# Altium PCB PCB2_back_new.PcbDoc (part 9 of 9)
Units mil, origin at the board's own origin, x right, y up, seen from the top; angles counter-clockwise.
Board outline 6299 x 3937 mil, 4 copper layers (TopLayer, GROUND, VCC, BottomLayer); 253 components, 421 nets, 2085 pads, 712 vias.
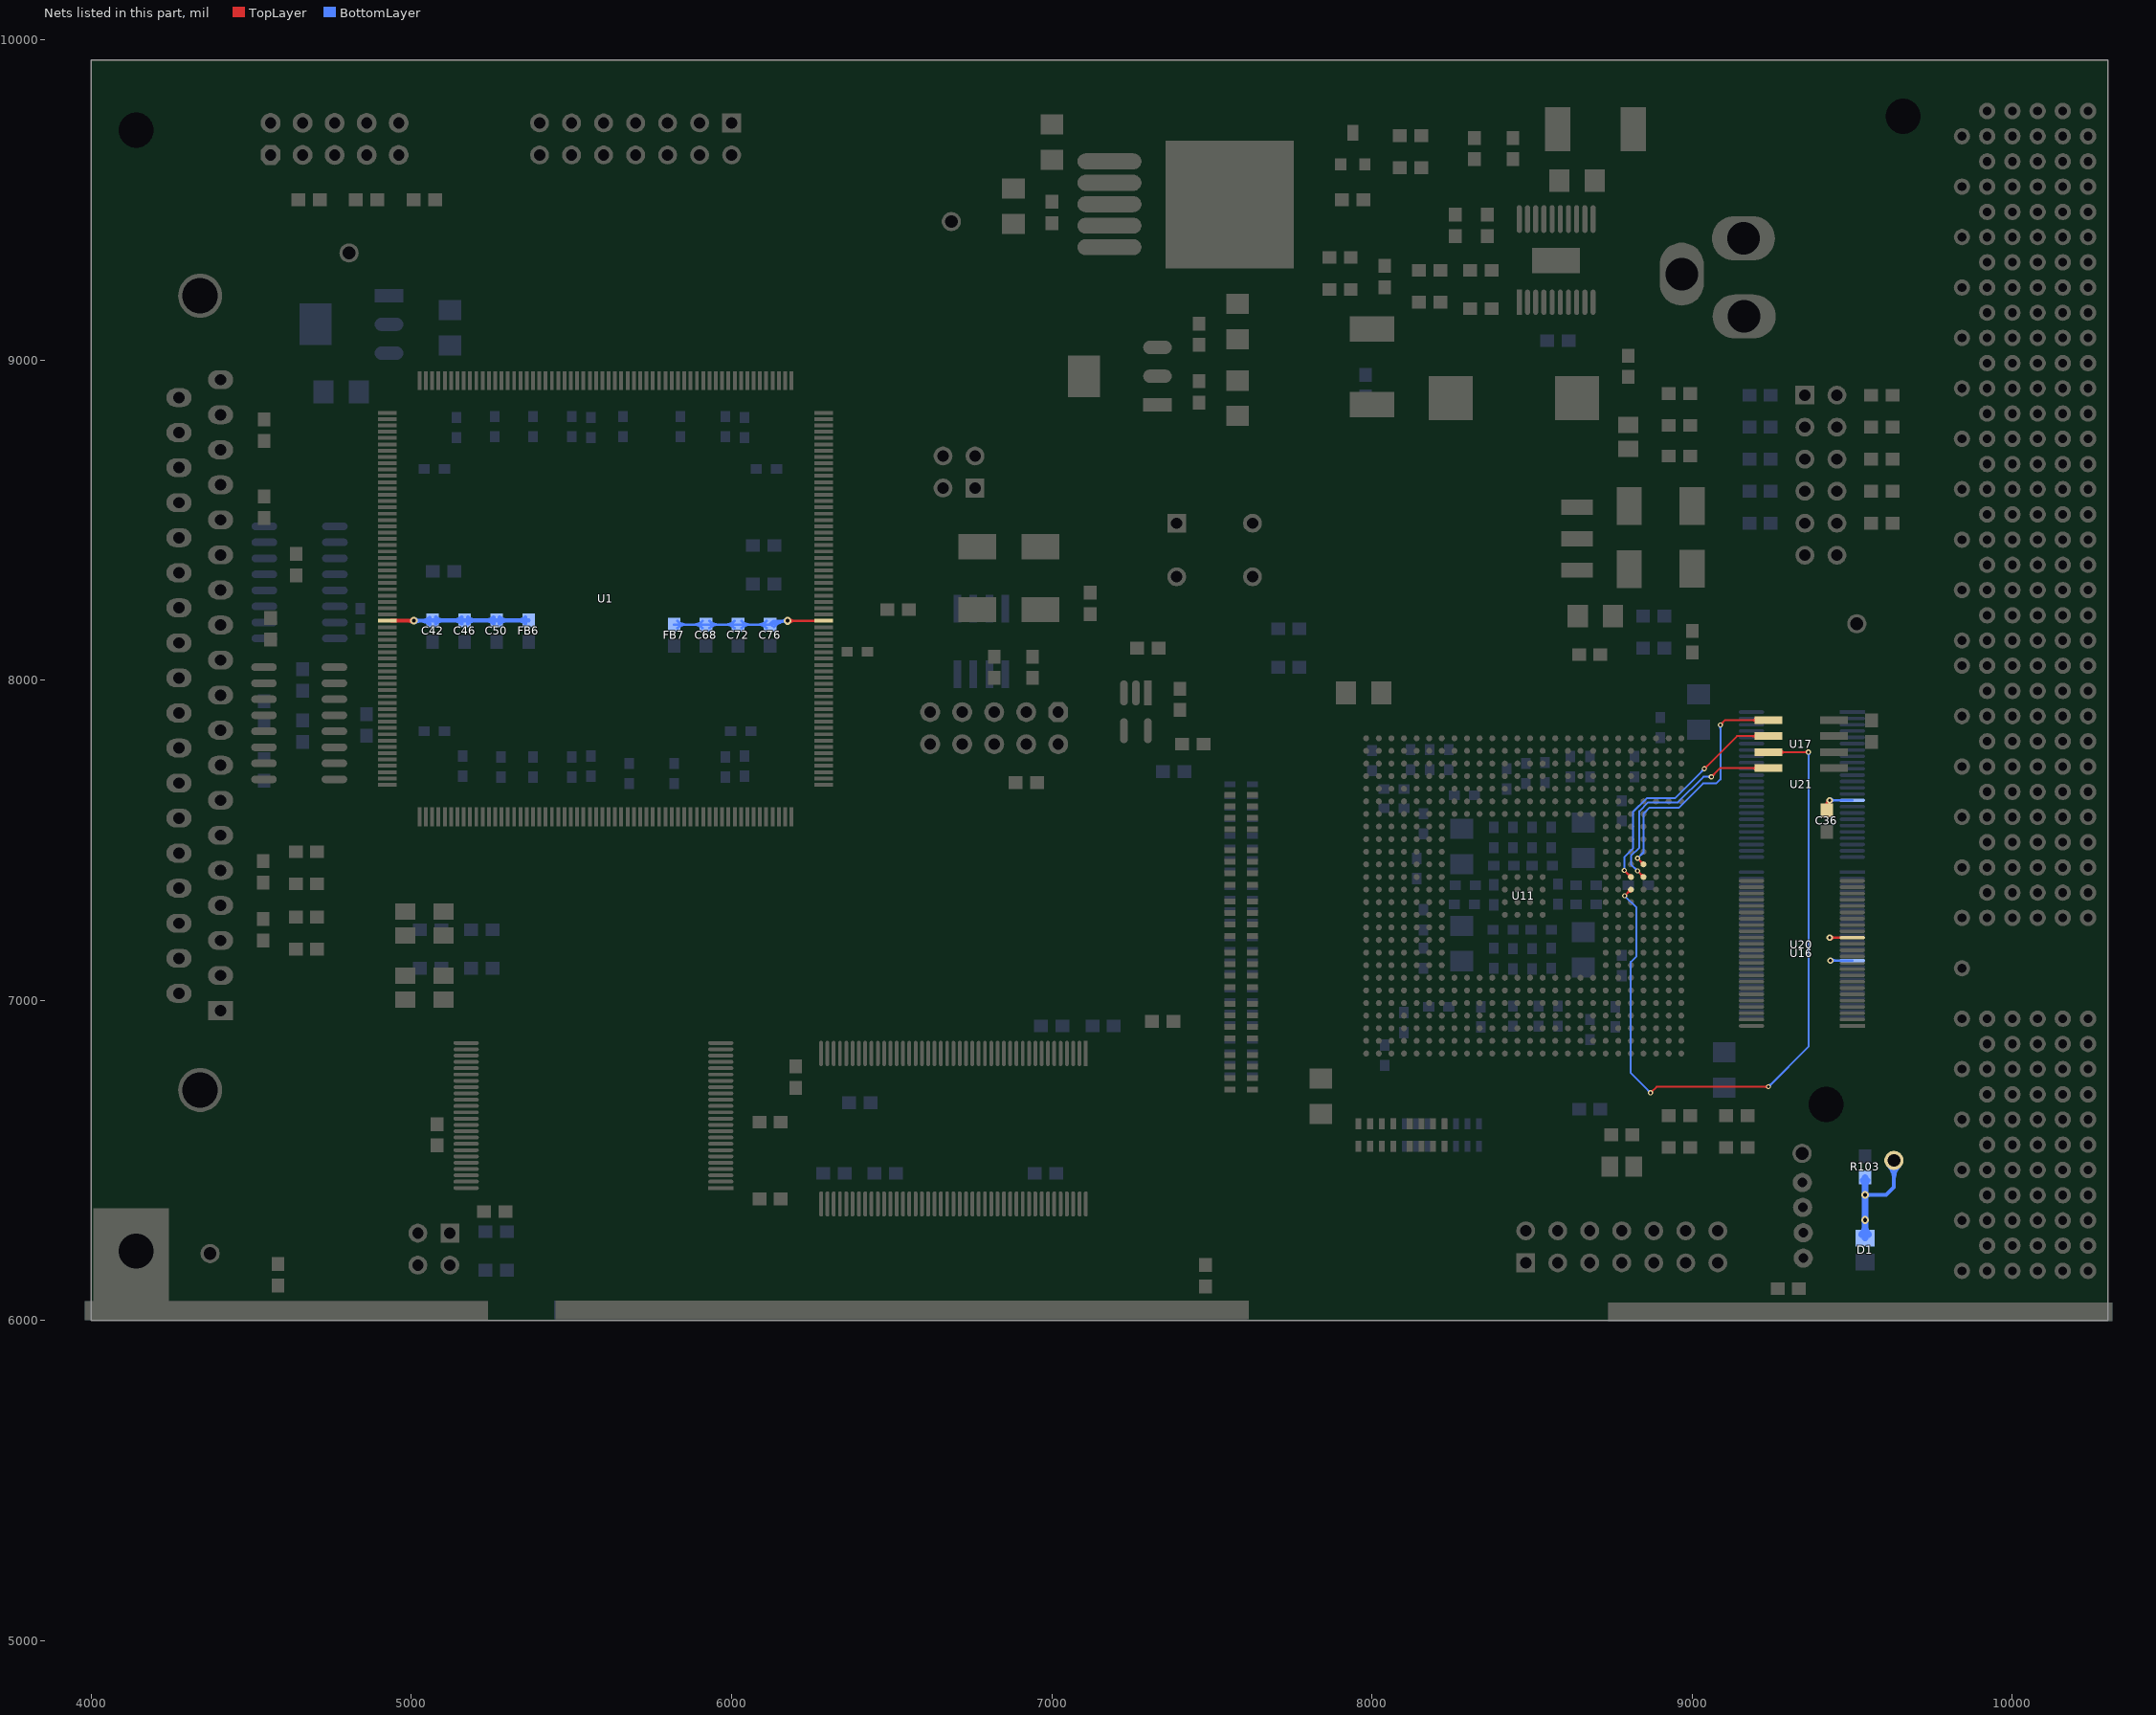
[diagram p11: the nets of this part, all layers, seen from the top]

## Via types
v1: diameter 16, hole 8, TopLayer to BottomLayer, 311 vias
v2: diameter 20, hole 10, TopLayer to BottomLayer, 202 vias
v3: diameter 24, hole 12, TopLayer to BottomLayer, 179 vias
v4: diameter 40, hole 20, TopLayer to BottomLayer, 12 vias
v5: diameter 30, hole 15, TopLayer to BottomLayer, 8 vias

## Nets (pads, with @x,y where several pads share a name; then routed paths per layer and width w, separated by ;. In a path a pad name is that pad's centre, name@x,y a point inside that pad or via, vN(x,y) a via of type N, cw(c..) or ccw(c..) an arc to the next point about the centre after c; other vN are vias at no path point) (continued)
V16210: C36.2 D1.2 pad.0@9630,6500 R103.1 U16.15 U20.15 U21.15 | length 966
  TopLayer w8: C36.2@9420,7592.07 cw(c9455.65,7592.07) v2@9433.19,7619.75 ; C36.2@9420,7593.46 C36.2@9420,7615 ; C36.2@9420,7608.86 cw(c9442.03,7608.86) v2@9428.15,7625.96 ; v2@9423.42,7624.04 cw(c9411.69,7623.31) C36.2@9420,7615 ; v2@9429.04,7618.42 ccw(c9428.31,7606.69) C36.2@9420,7615 ; v2(9429.41,7195.59) U16.15@9500,7195.59 ; v2(9429.41,7624.41) C36.2@9420,7615 ; v2@9433.65,7191.35 cw(c9443.9,7181.1) 9443.9,7195.59 cw(c9443.9,7210.08) v2@9433.65,7199.83
  BottomLayer w8: v2(9429.41,7624.41) U21.15@9500,7624.41 ; v2(9431.59,7124.41) U20.15@9500,7124.41 ; v2@9433.65,7620.17 cw(c9443.9,7609.92) 9443.9,7624.41 cw(c9443.9,7638.9) v2@9433.65,7628.65 ; v2@9435.83,7120.17 cw(c9446.08,7109.92) 9446.08,7124.41 cw(c9446.08,7138.9) v2@9435.83,7128.65
  BottomLayer w12: v3(9540,6392) 9605,6392 9630,6417 pad.0@9630,6500 ; v3@9544.24,6387.76 cw(c9554.49,6377.51) 9554.49,6392 cw(c9554.49,6406.49) v3@9544.24,6396.24 ; pad.0@9613.03,6483.03 cw(c9572.06,6442.06) 9630,6442.06 cw(c9687.94,6442.06) pad.0@9646.97,6483.03
  BottomLayer w20: D1.2@9528.98,6268.43 ccw(c9502.36,6295.04) 9540,6295.04 ccw(c9577.64,6295.04) D1.2@9551.02,6268.43 ; R103.1@9533.15,6437.72 cw(c9516.62,6421.19) 9540,6421.19 cw(c9563.38,6421.19) R103.1@9546.85,6437.72 ; D1.2@9540,6257.4 R103.1@9540,6446.54
  other v3: 9540,6314
VCCA_PLL1: C68.2 C72.1 C76.2 FB7.2 U1.27 | length 997.5
  TopLayer w8: v3(6175,8185) U1.27@6287.1,8185.1 ; v3@6180.66,8179.35 cw(c6194.33,8165.7) 6194.31,8185.02 cw(c6194.3,8204.33) v3@6180.65,8190.66
  BottomLayer w8: FB7.2@5820,8173.46 C76.2@6120,8173.46 6131.54,8185 v3(6175,8185) ccw(c6175,8128.17) C76.2@6131.9,8165.21 ; FB7.2@5831.09,8162.37 cw(c5857.87,8135.6) 5857.87,8173.46 cw(c5857.87,8211.33) FB7.2@5831.09,8184.56 ; C68.2@5908.91,8162.37 ccw(c5882.13,8135.6) 5882.13,8173.46 ccw(c5882.13,8211.33) C68.2@5908.91,8184.56 ; C68.2@5931.09,8162.37 cw(c5957.87,8135.6) 5957.87,8173.46 cw(c5957.87,8211.33) C68.2@5931.09,8184.56 ; C72.1@6008.91,8162.37 ccw(c5982.13,8135.6) 5982.13,8173.46 ccw(c5982.13,8211.33) C72.1@6008.91,8184.56 ; C72.1@6031.09,8162.37 cw(c6057.87,8135.6) 6057.87,8173.46 cw(c6057.87,8211.33) C72.1@6031.09,8184.56 ; C76.2@6108.91,8162.37 ccw(c6082.13,8135.6) 6082.13,8173.46 ccw(c6082.13,8211.33) C76.2@6108.91,8184.56 ; C76.2@6119.76,8175.64 cw(c6140.15,8158.12) 6140.15,8185 ; C76.2@6125.83,8170.42 cw(c6157.57,8143.14) 6157.57,8185 ; v3@6169.34,8179.34 ccw(c6155.69,8165.69) 6155.69,8185 ccw(c6155.69,8204.31) v3@6169.34,8190.66
VCCA_PLL2: C42.2 C46.2 C50.1 FB6.2 U1.154 | length 837.7
  TopLayer w12: U1.154@4937.69,8185.1 v3(5008.1,8185.1) ; v3@5003.86,8180.86 ccw(c4993.62,8170.62) 4993.62,8185.1 ccw(c4993.62,8199.59) v3@5003.86,8189.34
  BottomLayer w8: C42.2@5064.64,8185.1 C42.2@5066,8186.46
  BottomLayer w12: v3(5008.1,8185.1) C42.2@5064.64,8185.1 ; v3@5012.34,8180.86 cw(c5022.59,8170.62) 5022.59,8185.1 cw(c5022.59,8199.59) v3@5012.34,8189.34 ; 5031.5,8185.1 cw(c5031.5,8149.99) C42.2@5056.32,8174.82 ; 5034.43,8185.1 ccw(c5034.43,8216.07) C42.2@5056.32,8194.17 ; C42.2@5066,8186.46 FB6.2@5366,8186.46 ; C42.2@5075.68,8176.79 cw(c5099.04,8153.43) 5099.04,8186.46 cw(c5099.04,8219.5) C42.2@5075.68,8196.14 ; C46.2@5156.32,8176.79 ccw(c5132.96,8153.43) 5132.96,8186.46 ccw(c5132.96,8219.5) C46.2@5156.32,8196.14 ; C46.2@5175.68,8176.79 cw(c5199.04,8153.43) 5199.04,8186.46 cw(c5199.04,8219.5) C46.2@5175.68,8196.14 ; C50.1@5256.32,8176.79 ccw(c5232.96,8153.43) 5232.96,8186.46 ccw(c5232.96,8219.5) C50.1@5256.32,8196.14 ; C50.1@5275.68,8176.79 cw(c5299.04,8153.43) 5299.04,8186.46 cw(c5299.04,8219.5) C50.1@5275.68,8196.14 ; FB6.2@5356.32,8176.79 ccw(c5332.96,8153.43) 5332.96,8186.46 ccw(c5332.96,8219.5) FB6.2@5356.32,8196.14
XSPCLK: U11.R5 U17.2 | length 838.4
  TopLayer w6: v1(8788,7405.7) U11.R5@8808.52,7385.18 ; U11.R5@8802.27,7385.18 ccw(c8787.17,7385.18) 8797.85,7395.85 ccw(c8808.52,7406.53) U11.R5@8808.52,7391.43 ; v1(9038,7723) 9140,7825 U17.2@9237.64,7825 ; v1@9038,7728 ccw(c9038,7740.07) 9046.54,7731.54 ccw(c9055.07,7723) v1@9043,7723 ; U17.2@9199.91,7818.77 ccw(c9184.87,7803.73) 9184.87,7825 ccw(c9184.87,7846.27) U17.2@9199.91,7831.23
  BottomLayer w6: v1(8788,7405.7) 8788,7447 8815,7474 8815,7588 8858,7631 8946,7631 v1(9038,7723) ; v1@9033,7723 cw(c9020.93,7723) 9029.46,7714.46 cw(c9038,7705.93) v1@9038,7718
XSPCS: U11.T4 U17.1 | length 879.4
  TopLayer w6: v1(8829,7443.44) U11.T4@8847.89,7424.55 ; U11.T4@8841.64,7424.55 ccw(c8826.54,7424.55) 8837.22,7435.22 ccw(c8847.89,7445.9) U11.T4@8847.89,7430.8 ; v1(9088,7860) 9103,7875 U17.1@9237.64,7875 ; v1@9088,7865 ccw(c9088,7877.07) 9096.54,7868.54 ccw(c9105.07,7860) v1@9093,7860 ; U17.1@9199.91,7868.77 ccw(c9184.87,7853.73) 9184.87,7875 ccw(c9184.87,7896.27) U17.1@9199.91,7881.23
  BottomLayer w6: v1(8829,7443.44) 8848,7462.44 8848,7583 8867,7602 8959,7602 9034,7677 9075,7677 9088,7690 v1(9088,7860) ; v1@9084.46,7856.46 cw(c9075.93,7847.93) 9088,7847.93 cw(c9100.07,7847.93) v1@9091.54,7856.46
XSPDI: U11.R4 U17.4 | length 785.9
  TopLayer w6: v1(8829,7404.07) U11.R4@8847.89,7385.18 ; U11.R4@8841.64,7385.18 ccw(c8826.54,7385.18) 8837.22,7395.85 ccw(c8847.89,7406.53) U11.R4@8847.89,7391.43 ; v1(9060,7698) 9087,7725 U17.4@9237.64,7725 ; v1@9060,7703 ccw(c9060,7715.07) 9068.54,7706.54 ccw(c9077.07,7698) v1@9065,7698 ; U17.4@9199.91,7718.77 ccw(c9184.87,7703.73) 9184.87,7725 ccw(c9184.87,7746.27) U17.4@9199.91,7731.23
  BottomLayer w6: v1(8829,7404.07) 8809,7424.07 8809,7451.03 8834.82,7476.85 8834.82,7590.82 8862,7618 8955,7618 9035,7698 v1(9060,7698) ; v1@9056.46,7694.46 ccw(c9047.93,7685.93) 9047.93,7698 ccw(c9047.93,7710.07) v1@9056.46,7701.54
XSPDO: U11.P5 U17.3 | length 2461.1
  TopLayer w6: v1(8789,7326.29) U11.P5@8808.52,7345.81 ; U11.P5@8802.27,7345.81 cw(c8787.17,7345.81) 8797.85,7335.14 cw(c8808.52,7324.47) U11.P5@8808.52,7339.56 ; v1(8870,6711) 8889,6730 v1(9238,6730) ; v1@8870,6716 ccw(c8870,6728.07) 8878.54,6719.54 ccw(c8887.07,6711) v1@8875,6711 ; v1@9234.46,6726.46 ccw(c9225.93,6717.93) 9225.93,6730 ccw(c9225.93,6742.07) v1@9234.46,6733.54 ; U17.3@9237.64,7775 v1(9363,7775) ; U17.3@9275.36,7768.77 cw(c9290.41,7753.73) 9290.41,7775 cw(c9290.41,7796.27) U17.3@9275.36,7781.23 ; v1@9359.46,7771.46 ccw(c9350.93,7762.93) 9350.93,7775 ccw(c9350.93,7787.07) v1@9359.46,7778.54
  BottomLayer w6: v1(8789,7326.29) 8826,7289.29 8826,7138 8808,7120 8808,6773 v1(8870,6711) ; v1@8865,6711 ccw(c8852.93,6711) 8861.46,6719.54 ccw(c8870,6728.07) v1@8870,6716 ; v1(9238,6730) 9364,6856 9364,7774 v1(9363,7775) ; v1@9238,6735 ccw(c9238,6747.07) 9246.54,6738.54 ccw(c9255.07,6730) v1@9243,6730 ; v1@9359.46,7771.46 cw(c9348.51,7760.51) 9364,7760.51 ; 9364,7765.34 cw(c9372.66,7765.34) v1@9366.54,7771.46
pads on no net: J2.6 J4.A15 J4.A17 J4.A19 J4.A21 J4.A23 J4.C8 J4.C10 J4.C16 J4.C18 J4.C20 J4.C22 J4.C24 J4.D25 J5.A1 J5.A2 J5.A3 J5.A4 J5.A5 J5.A6 J5.A7 J5.A8 J5.A9 J5.A10 J5.A11 J5.A12 J5.A13 J5.A14 J5.A15 J5.A19 J5.A20 J5.A21 J5.A22 J5.B2 J5.B4 J5.B5 J5.B6 J5.B8 J5.B10 J5.B12 J5.B14 J5.B19 J5.B20 J5.B21 J5.B22 J5.C1 J5.C2 J5.C3 J5.C4 J5.C5 J5.C6 J5.C7 J5.C8 J5.C9 J5.C10 J5.C11 J5.C12 J5.C13 J5.C14 J5.C15 J5.C16 J5.C17 J5.C19 J5.C20 J5.C21 J5.C22 J5.D1 J5.D2 J5.D3 J5.D5 J5.D7 J5.D9 J5.D11 J5.D13 J5.D15 J5.D19 J5.D21 J5.D22 J5.E1 J5.E2 J5.E3 J5.E4 J5.E5 J5.E6 J5.E7 J5.E8 J5.E9 J5.E10 J5.E11 J5.E12 J5.E13 J5.E14 J5.E15 J5.E19 J5.E20 J5.E21 J5.E22 JP1.0 JP1.2 JP1.3 JP1.17 JP1.19 JP1.21 JP1.35 JP1.37 JP8.6 JP8.7 JP8.8 S2.3 S2.4 U1.23 U1.38 U1.45 U1.46 U1.47 U1.48 U1.49 U1.50 U1.53 U1.54 U1.55 U1.56 U1.57 U1.58 U1.59 U1.60 U1.61 U1.62 U1.63 U1.64 U1.65 U1.66 U1.67 U1.68 U1.73 U1.74 U1.75 U1.76 U1.77 U1.78 U1.79 U1.104 U1.105 U1.106 U1.107 U1.108 U1.113 U1.114 U1.115 U1.116 U1.117 U1.118 U1.119 U1.120 U1.121 U1.122 U1.123 U1.124 U1.125 U1.126 U1.127 U1.128 U1.131 U1.132 U1.133 U1.134 U1.135 U1.138 U1.143 U1.144 U1.156 U1.158 U1.164 U1.165 U1.166 U1.167 U1.168 U1.169 U1.170 U1.175 U1.176 U2.9 U2.10 U2.13 U2.14 U2.15 U2.30 U2.32 U2.34 U2.36 U2.39 U2.41 U2.43 U4.14 U4.30 U4.57 U4.69 U4.70 U4.73 U6.1 U7.5 U11.A4 U11.A5 U11.A7 U11.A9 U11.A10 U11.A11 U11.A13 U11.A17 U11.AA2 U11.AA3 U11.AA23 U11.AA24 U11.AA25 U11.AA26 U11.AB3 U11.AB11 U11.AB12 U11.AB13 U11.AB14 U11.AB15 U11.AB16 U11.AB23 U11.AB24 U11.AB25 U11.AC1 U11.AC4 U11.AC6 U11.AC7 U11.AC8 U11.AC9 U11.AC10 U11.AC11 U11.AC12 U11.AC13 U11.AC14 U11.AC15 U11.AC16 U11.AC17 U11.AC19 U11.AC20 U11.AC21 U11.AC25 U11.AC26 U11.AD3 U11.AD5 U11.AD6 U11.AD7 U11.AD8 U11.AD9 U11.AD10 U11.AD11 U11.AD12 U11.AD13 U11.AD14 U11.AD15 U11.AD16 U11.AD17 U11.AD19 U11.AD20 U11.AD21 U11.AD22 U11.AD23 U11.AD25 U11.AD26 U11.AE5 U11.AE6 U11.AE7 U11.AE9 U11.AE11 U11.AE15 U11.AE16 U11.AE17 U11.AE18 U11.AE20 U11.AE21 U11.AE22 U11.AE23 U11.AF3 U11.AF4 U11.AF5 U11.AF6 U11.AF8 U11.AF10 U11.AF12 U11.AF14 U11.AF16 U11.AF17 U11.AF18 U11.AF20 U11.AF21 U11.AF23 U11.AF24 U11.B8 U11.B9 U11.B10 U11.B11 U11.B12 U11.B15 U11.B16 U11.B17 U11.C7 U11.C8 U11.C9 U11.C10 U11.C11 U11.C12 U11.C15 U11.C16 U11.C17 U11.D6 U11.D7 U11.D8 U11.D9 U11.D10 U11.D11 U11.D12 U11.D15 U11.D16 U11.D17 U11.E11 U11.E12 U11.E13 U11.E14 U11.L22 U11.M5 U11.M22 U11.N22 U11.P22 U11.R22 U11.R25 U11.R26 U11.T22 U11.T23 U11.W7 U11.W23 U11.W24 U11.Y23 U11.Y24 U11.Y25 U11.Y26 U15.1 U16.1 U17.6 U17.7 U20.1 U21.1 U21.36 U21.37 U21.38 U21.39 U21.40 U21.42 U21.43 U21.44 U21.45 U21.46

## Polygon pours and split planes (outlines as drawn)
GND on GROUND (split plane): 10266.92,6032.08 4243,6032.08 4243,6324 4026.08,6324 4026.08,9610 4245,9610 4245,9906.92 10266.92,9906.92
V3.3 on VCC (split plane): 296 vertices, not listed, extent 4086.08,6085.08 9679.93,9855.92
V5 on VCC (split plane): 10262.92,6085.08 9358.07,6085.08 9358.07,6254.93 9695,6254.93 9697.94,6255.22 9700.77,6256.07 9703.37,6257.47 9705.66,6259.34 9707.53,6261.63 9708.93,6264.23 9709.78,6267.06 9710.07,6270 9710.07,7694 9710.07,8111 9709.78,8113.94 9708.93,8116.77 9707.53,8119.37 9705.66,8121.66 9703.37,8123.53 9700.77,8124.93 9697.94,8125.78 9695,8126.07 9251.07,8126.07 9251.07,8972 9250.78,8974.94 9249.93,8977.77 9248.53,8980.37 9246.66,8982.66 9244.37,8984.53 9241.77,8985.93 9238.94,8986.78 9236,8987.07 8257,8987.07 8256.99,8987.07 7800.99,8986.77 7800.94,8986.78 7798,8987.07 7795.06,8986.78 7795,8986.76 6754.99,8986.07 6753.49,8985.92 6752.06,8985.78 6752.05,8985.78 6750.66,8985.36 6749.54,8985.02 6749,8985.07 4956.07,8985.07 4956.07,9145.93 7334,9145.93 7336.94,9146.22 7339.77,9147.07 7342.37,9148.47 7344.66,9150.34 7346.53,9152.63 7347.93,9155.23 7348.78,9158.06 7349.07,9161 7349.07,9483 7348.78,9485.94 7347.93,9488.77 7346.53,9491.37 7344.66,9493.66 7342.37,9495.53 7339.77,9496.93 7336.94,9497.78 7334,9498.07 6894.07,9498.07 6894.07,9855.92 10262.92,9855.92
V1.5 on VCC (split plane): 7782.93,8911 7782.93,8599.07 7627,8599.07 7624.06,8598.78 7621.23,8597.93 7618.63,8596.53 7616.34,8594.66 7388.76,8367.07 6535,8367.07 6532.06,8366.78 6529.23,8365.93 6526.63,8364.53 6524.34,8362.66 6007.34,7845.66 6005.47,7843.37 6004.07,7840.77 6003.22,7837.94 6002.93,7835 6002.93,7706.07 5206.07,7706.07 5206.07,7884.76 5281.66,7960.34 5283.53,7962.63 5284.93,7965.23 5285.78,7968.06 5286.07,7971 5286.07,8328 5285.78,8330.94 5284.93,8333.77 5283.53,8336.37 5281.66,8338.66 5177.07,8443.24 5177.07,8798.93 6114.93,8798.93 6114.93,8594 6115.22,8591.06 6116.07,8588.23 6117.47,8585.63 6119.34,8583.34 6121.63,8581.47 6124.23,8580.07 6127.06,8579.22 6130,8578.93 6378,8578.93 6380.94,8579.22 6383.77,8580.07 6386.37,8581.47 6388.66,8583.34 6761.25,8955.93 7782.93,8956.61
V1.4 on VCC (split plane): 153 vertices, not listed, extent 7813.07,7016.09 8794.91,8956.92
V16210 on VCC (split plane): 9679.93,6285.07 9358.07,6285.07 9358.07,6727 9358.07,7678.93 9679.93,7678.93

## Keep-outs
KeepOutLayer:
  lines w8: 4064,6393 4065,9619 4240,9619 4240,9819 10090,9819 10240,9819 10276,9819 10276,6119 10240,6119 9766,6119

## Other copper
TopLayer:
  rectangle net V3.3: 6848,9295 6914,9400
  rectangle net V3.3: 6776,9400 7139,9438
  rectangle net GND: 8459,9271 8507,9350
  rectangle net GND: 8638,9272 8691,9471
  rectangle net V5: 8566,9404 8613,9686
  rectangle net NetC118_2: 8590,8909 8693,9203
  rectangle net V1.4: 7884,8829 8225,8889
  rectangle net V5: 8601,9666 8664,9773
BottomLayer:
  text "P/N XXXXXX-XXX REV A" at 5320,10137 h40
GROUND (plane layer: these items are gaps in the copper):
  rectangle: 4018,6007 4243,6324
  rectangle: 4014,9610 4245,9916
  lines w50: 4001,6032 4001,9932 10292,9932 10292,6007 4001,6007 4001,6070
VCC (plane layer: these items are gaps in the copper):
  rectangle: 4058,6067 4238,6327
  rectangle: 4075,9623 4239,9868
  lines w20: 7798,8584 8002,8584 8002,7958 8264,7696 8393,7696 8432,7657 8432,7605 8255,7605 8216,7644 8154,7644 8154,7536 8192,7498 8192,7476 8164,7448 8164,7409 8198,7375 8198,7323 8228,7293 8228,7277 8160,7209 8160,7026 8180,7006 8195,7006 8242,7053 8668,7053 8710,7011 8782,7011 8805,7034 8805,7059 8735,7129 8735,7154 8783,7202 8783,7223 8755,7251 8725,7251 8725,7356 8772,7403 8772,7472 8753,7491 8753,7563 8789,7599 8789,7641 8677,7641 8677,7602 8526,7602 8526,7740 8257,8009 8257,8972
  lines w30: 6749,8970 4941,8970 4941,9161 7334,9161 7334,9483 6879,9483 6879,9482 ; 6879,9906 6879,9482 ; 6881,9482 6879,9482 ; 7798,8972 7798,8911 7798,8584 7627,8584 7395,8352 6535,8352 6018,7835 6018,7691 5191,7691 5191,7891 5271,7971 5271,8328 5162,8437 5162,8814 6130,8814 6130,8803 6130,8594 6303,8594 6378,8594 6755,8971 8257,8972 9236,8972 9236,8111 9695,8111 9695,7694 ; 9333.46,6026.54 9343,6036.07 9343,6727 ; 9343,6270 9695,6270 9695,7694 ; 9343,6667 9343,7694 9695,7694 ; 9647,7694 9695,7694
  lines w50: 10288,6035 10288,9906
  lines w100: 10288,6035 9695,6035 4036,6035 4036,9906 10288,9906

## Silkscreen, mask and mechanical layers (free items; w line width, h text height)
TopOverlay:
  circle w10: c4140,9717 r112.5
  circle w10: c9659,9761 r112.5
  circle w10: c9418,6675 r112.5
  lines w10: 5392.59,10732.97 ccw(c5441,10772.5) 5392.71,10732.83
  text "FPGA JTAG" at 4230,9498 h40
  text "3.3V" at 6543,9450 h40
  text "GND" at 4859,9311 h40
  text "1.4V" at 7932,8702 h40
  text "test IO" at 6411,8476 h40
  text "RESET" at 7155,8475 h40
  text "50MHz" at 9064,8314 h40
  text "GND" at 9584,8152 h40
  text "FPGA AS" at 6559,7679 h40
  text "ECLKOUT1" at 7042,6990 h40
  text "LENDIAN" at 8659,6643 h40
  text "PCI_EN" at 9271,6617 h40 r90
  text "4.3V" at 9592,6547 h30
  text "GND" at 9394,6513 h40
  text "GP02" at 8538,6506 h40
  text "NMI" at 9061,6444 h40
  text "PXI_3.3V" at 9384,6421 h40
  text "PXI_VIO" at 9383,6339 h40
  text "EA21" at 4790,6258 h40
  text "PXI_-12V" at 9397,6253 h40
  text "PXI_+12V" at 9400,6180 h40
  text "EA22" at 4771,6151 h40
  text "DSP JTAG" at 8041,6145 h40
  text "GND" at 4318,6120 h40
  text "DSP BOOT MODE" at 4909,6076 h40
BottomOverlay:
  text "V3.3" at 6636,9391 h30
  text "2.5V" at 4637,8817 h40 r180
  text "PCI66" at 9135,8188 h40
  text "EEAI" at 8708,6722 h40
TopSolder:
  lines w60: 4003,6033 10290,6031
BottomSolder:
  lines w60: 4003,6031 10290,6029
Mechanical1:
  the board outline again, w20
Mechanical4:
  lines w19.68: 10310.04,9162.4 10556.1,9162.4 ; 10311.02,7981.3 10425.2,7981.3 ; 10315.94,9712.6 10562.01,9712.6
  text ".Pcb_File_Name_No_Path" at 8099,10277 h40
  text ".Printout_Name" at 8099,10087 h40
  text "90.45" at 10635.83,9682.09 h40
  text "76.45" at 10638.78,9129.92 h40
  text "46.45" at 10452.76,7801.18 h40

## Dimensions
4140,5980 to 4000,6000 on Mechanical4
3980,6217 to 4000,6000 on Mechanical4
